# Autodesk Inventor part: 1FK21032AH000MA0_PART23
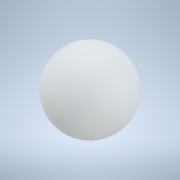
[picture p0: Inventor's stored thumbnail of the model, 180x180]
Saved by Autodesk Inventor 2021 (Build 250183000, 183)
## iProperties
Created: 2025-04
Part Number: 1FK21032AH000MA0_PART23
Material: Generic
Catalog Web Link: www.3dfindit.com
Description: -Servo synchronous motor
Document SubType Name: Modeling
Designer: psAdmin
Mass: 0.113097 g
Surface Area: 1.13097 cm^2
Volume: 0.113097 cm^3
Density: 1 g/cm^3
Appearance: PSOLRGB-212-217-219
Category: PARTsolutions
Title: 1FK21032AH000MA0_PART23
Author: Cadenas PARTsolutions
Comments: Servo synchronous motor
Sending System: PARTsolutions
Preprocessor: ST-DEVELOPER v19.3
PSOL_IDENT_0: {$CADENAS_DATA/23d-libs/siemens_ag/_cat_/45/10/1fk21032ah000ma0.prj},216 {VTYP=3D},{NB=1FK21032AH000
PSOL_IDENT_1: MA0_PART23},{LINA=1FK21032AH000MA0_PART23},{NN=1FK21032AH000MA0_PART23},{NOPRJ=TRUE},{DATE=19.08.202
PSOL_IDENT_2: 5 14:00:35},{GEOMDATE=30.07.2025 02:02:03},{VERSION=},{LINEID=10},{WBVAR=},{WBNUMERIC=}  {NB=1FK2103
PSOL_IDENT_3: 2AH000MA0_PART23},{LINA=1FK21032AH000MA0_PART23},{KT=DUMMY},{PREVIEW=../../../_pool_/14/8e/p_d211_xx
PSOL_IDENT_4: _00426j.png},{DESCSHORT=SIMOTICS S-1FK2 HD, SINAMICS S210 3AC 400V-480V, 0.59 Nm, 4500 rpm},{DESCLON
PSOL_IDENT_5: G=SIMOTICS S-1FK2 HD servo motor M0=0.64 Nm; PN = 0.28 kW at nN=4500 rpm (380-480 V); PN = 0.167 kW
PSOL_IDENT_6: at nN=2500 rpm (200-240 V); degree of protection IP64; cylindrical shaft D14 x 30 mm; absolute encod
PSOL_IDENT_7: er 22-bit + 12-bit multiturn (encoder AM22DQC); with OCC interface; plug size M17, rotatable; SIMOTI
PSOL_IDENT_8: CS S-1FK2 servomotorfor a wide range of uses in industrial environments. SIMOTICS S‑1FK2 servomotors
PSOL_IDENT_9: are compact synchronous motors with a high dynamic performance that set themselves apart as a resul
PSOL_IDENT_10: t of their high power density, degree of protection and overload capability. The motors are availabl
PSOL_IDENT_11: e in two variants: as High Dynamic variant (highest dynamic performance as a result of the low intri
PSOL_IDENT_12: nsic moment of inertia for applications demanding a high dynamic performance with low moved masses)
PSOL_IDENT_13: - and as Compact variant (precise and stable closed-loop control for medium up to large moved masses
PSOL_IDENT_14: as a result of a medium intrinsic moment of inertia). SIMOTICSS‑1FK2 servomotors fully exploit thei
PSOL_IDENT_15: r strengths in a system with the SINAMICSS210 frequency converter and simple connection using the on
PSOL_IDENT_16: e cable connection (OCC). Advantages include the short control and positioning times, fast and preci
PSOL_IDENT_17: se correction of disturbing quantities as well as stable control with a high dynamic performance. Th
PSOL_IDENT_18: e servo motors can be configured to address a wide range of requirements. For example with and witho
PSOL_IDENT_19: ut holding brake, IP64 or IP65 degree of protection, singleturn or multiturn absolute encoders - to
PSOL_IDENT_20: name just a few. Further, the servomotors are available in different shaft heights extending from 20
PSOL_IDENT_21: to 100. A shaft sealing ring is available to achieve an IP65 degree of protection and for subsequen
PSOL_IDENT_22: t mounting at the motor or as spare part. SIMOTICS - the optimum motor for each and every motion con
PSOL_IDENT_23: trol application.},{INTNO=195125335004},{SUPPLIERALTNO=1FK2103-2AH00-0MA0},{MANUID=1FK21032AH000MA0}
PSOL_IDENT_24: ,{MANUNAME=Siemens},{MANUTYPEDESC=SYNCHRONOUS MOTOR 1FK2 HD 0,64 NM},{AAU732=SIMOTICS},{AAO057=S-1FK
PSOL_IDENT_25: 2},{AAU734=SIMOTICS S-1FK2 HD servo motor M0=0.64 Nm; PN = 0.28 kW at nN=4500 rpm (380-480 V); PN =
PSOL_IDENT_26: 0.167 kW at nN=2500 rpm (200-240 V); degree of protection IP64; cylindrical shaft D14 x 30 mm; absol
PSOL_IDENT_27: ute encoder 22-bit + 12-bit multiturn (encoder AM22DQC); with OCC interface; plug size M17, rotatabl
PSOL_IDENT_28: e;},{AAW338=SYNCHRONOUS MOTOR 1FK2 HD 0,64 NM},{AAO742=SIMOTICS},{AAO663=4034106444624},{NOCUPEROU=1
PSOL_IDENT_29: },{PRICEQUANTITY=1},{QUANTITYMIN=1},{QUANTITYINT=1},{CTN=85015100},{COO=RO},{AAO676=1FK2103-2AH00-0M
PSOL_IDENT_30: A0},{AAO677=Siemens AG},{ORDERUNIT=C62},{CONTENTUNIT=C62}
NB: 1FK21032AH000MA0_PART23
NT: Servo synchronous motor
NBSYN: $MANUID._PART23
LINA: 1FK21032AH000MA0_PART23
CATALOG: SIEMENS
PREVIEW: ../../../_pool_/14/8e/p_d211_xx_00426j.png
DESCSHORT: SIMOTICS S-1FK2 HD, SINAMICS S210 3AC 400V-480V, 0.59 Nm, 4500 rpm
DESCLONG: SIMOTICS S-1FK2 HD servo motor M0=0.64 Nm; PN = 0.28 kW at nN=4500 rpm (380-480 V); PN = 0.167 kW at nN=2500 rpm (200-240 V); degree of protection IP64; cylindr
INTNO: 195125335004
SUPPLIERALTNO: 1FK2103-2AH00-0MA0
MANUID: 1FK21032AH000MA0
MANUNAME: Siemens
MANUTYPEDESC: SYNCHRONOUS MOTOR 1FK2 HD 0,64 NM
AAU732: SIMOTICS
AAO057: S-1FK2
AAU734: SIMOTICS S-1FK2 HD servo motor M0=0.64 Nm; PN = 0.28 kW at nN=4500 rpm (380-480 V); PN = 0.167 kW at nN=2500 rpm (200-240 V); degree of protection IP64; cylindr
AAW338: SYNCHRONOUS MOTOR 1FK2 HD 0,64 NM
AAO742: SIMOTICS
AAO663: 4034106444624.0
NOCUPEROU: 1
PRICEQUANTITY: 1
QUANTITYMIN: 1
QUANTITYINT: 1
CTN: 85015100
COO: RO
ARTICLENO: 1FK21032AH000MA0_PART23
BOMINFO: 1FK21032AH000MA0_PART23
CREATOR: CADENAS GmbH
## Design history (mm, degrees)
feature "2025_04_17_15_00_20_0760"
body "Solid1"
